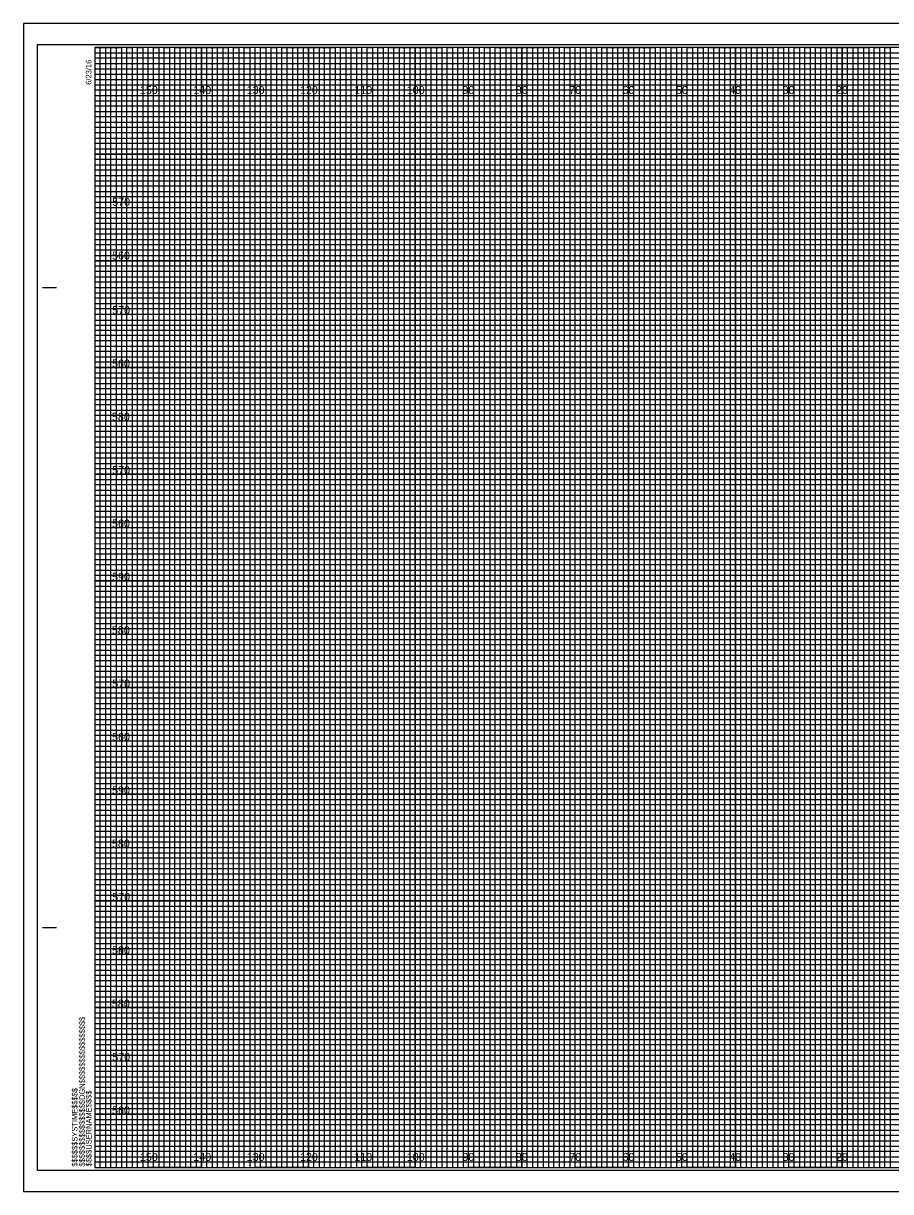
# Model space of a CAD drawing. Extents: x -13 to 323, y -5 to 215.
# Drawn here: x -13.4 to 149.1, y -4.5 to 214.5 of the extents above; entities that cross this region are included whole.
import ezdxf

# ---------------------------------------------------------------- set-up
doc = ezdxf.new("R2010")
doc.units = 0
for name, color, linetype in [('Exist Cross Section Cell', 7, 'Continuous'), ('Exist XS Center Line Elevation Label', 7, 'Continuous'), ('Exist XS Ground Line', 7, 'Continuous'), ('Prop XS Ditch Standard Text', 7, 'Continuous'), ('Prop XS Dump Level', 7, 'Continuous'), ('Prop XS Finish Grade', 7, 'Continuous'), ('Prop XS Finish Grade Earthwork', 7, 'Continuous'), ('Prop XS SE Text', 7, 'Continuous'), ('Prop XS Side Slope Text', 7, 'Continuous'), ('Prop XS SS Elevation Text', 7, 'Continuous'), ('Prop XS Subgrade Earthwork', 7, 'Continuous')]:
    doc.layers.add(name, color=color, linetype=linetype)

msp = doc.modelspace()

# ---------------------------------------------------------------- linework, layer by layer
at = {"layer": 'Exist Cross Section Cell'}
for points in [[(0, 210), (5, 210), (5, 0), (15, 0), (15, 210), (25, 210), (25, 0), (35, 0), (35, 210), (45, 210), (45, 0), (55, 0), (55, 210), (65, 210), (65, 0), (75, 0), (75, 210), (85, 210), (85, 0), (95, 0), (95, 210), (105, 210), (105, 0), (115, 0), (115, 210), (125, 210), (125, 0), (135, 0), (135, 210), (145, 210), (145, 0), (155, 0)], [(0, 205), (275, 205)], [(0, 185), (320, 185), (320, 195), (0, 195)], [(0, 165), (320, 165), (320, 175), (0, 175)], [(0, 145), (320, 145), (320, 155), (0, 155)], [(0, 125), (320, 125), (320, 135), (0, 135)], [(0, 105), (320, 105), (320, 115), (0, 115)], [(0, 85), (320, 85), (320, 95), (0, 95)], [(0, 65), (320, 65), (320, 75), (0, 75)], [(0, 45), (320, 45), (320, 55), (0, 55)], [(0, 25), (320, 25), (320, 35), (0, 35)], [(0, 5), (320, 5), (320, 15), (0, 15)]]:
    msp.add_lwpolyline(points, dxfattribs=at)
at = {"layer": 'Exist XS Center Line Elevation Label'}
for p, q in [((10, 210), (0, 210)), ((10, 0), (10, 210)), ((30, 210), (20, 210)), ((20, 210), (20, 0)), ((30, 0), (30, 210)), ((50, 210), (40, 210)), ((40, 210), (40, 0)), ((50, 0), (50, 210)), ((70, 210), (60, 210)), ((60, 210), (60, 0)), ((70, 0), (70, 210)), ((90, 210), (80, 210)), ((80, 210), (80, 0)), ((90, 0), (90, 210)), ((110, 210), (100, 210)), ((100, 210), (100, 0)), ((110, 0), (110, 210)), ((130, 210), (120, 210)), ((120, 210), (120, 0)), ((130, 0), (130, 210)), ((150, 210), (140, 210)), ((140, 210), (140, 0)), ((20, 0), (10, 0)), ((40, 0), (30, 0)), ((60, 0), (50, 0)), ((80, 0), (70, 0)), ((100, 0), (90, 0)), ((120, 0), (110, 0)), ((140, 0), (130, 0))]:
    msp.add_line(p, q, dxfattribs=at)
for points in [[(0, 200), (320, 200), (320, 190), (0, 190)], [(0, 180), (320, 180), (320, 170), (0, 170)], [(0, 160), (320, 160), (320, 150), (0, 150)], [(0, 140), (320, 140), (320, 130), (0, 130)], [(0, 120), (320, 120), (320, 110), (0, 110)], [(0, 100), (320, 100), (320, 90), (0, 90)], [(0, 80), (320, 80), (320, 70), (0, 70)], [(0, 60), (320, 60), (320, 50), (0, 50)], [(0, 40), (320, 40), (320, 30), (0, 30)], [(0, 20), (320, 20), (320, 10), (0, 10)]]:
    msp.add_lwpolyline(points, dxfattribs=at)
at = {"layer": 'Prop XS Ditch Standard Text'}
for points in [[(0, 0), (1, 0), (1, 210), (2, 210), (2, 0)], [(2, 0), (3, 0), (3, 210), (4, 210), (4, 0)], [(5, 0), (6, 0), (6, 210), (7, 210), (7, 0)], [(7, 0), (8, 0), (8, 210), (9, 210), (9, 0)], [(10, 0), (11, 0), (11, 210), (12, 210), (12, 0)], [(12, 0), (13, 0), (13, 210), (14, 210), (14, 0)], [(15, 0), (16, 0), (16, 210), (17, 210), (17, 0)], [(17, 0), (18, 0), (18, 210), (19, 210), (19, 0)], [(20, 0), (21, 0), (21, 210), (22, 210), (22, 0)], [(22, 0), (23, 0), (23, 210), (24, 210), (24, 0)], [(25, 0), (26, 0), (26, 210), (27, 210), (27, 0)], [(27, 0), (28, 0), (28, 210), (29, 210), (29, 0)], [(30, 0), (31, 0), (31, 210), (32, 210), (32, 0)], [(32, 0), (33, 0), (33, 210), (34, 210), (34, 0)], [(35, 0), (36, 0), (36, 210), (37, 210), (37, 0)], [(37, 0), (38, 0), (38, 210), (39, 210), (39, 0)], [(40, 0), (41, 0), (41, 210), (42, 210), (42, 0)], [(42, 0), (43, 0), (43, 210), (44, 210), (44, 0)], [(45, 0), (46, 0), (46, 210), (47, 210), (47, 0)], [(47, 0), (48, 0), (48, 210), (49, 210), (49, 0)], [(50, 0), (51, 0), (51, 210), (52, 210), (52, 0)], [(52, 0), (53, 0), (53, 210), (54, 210), (54, 0)], [(55, 0), (56, 0), (56, 210), (57, 210), (57, 0)], [(57, 0), (58, 0), (58, 210), (59, 210), (59, 0)], [(60, 0), (61, 0), (61, 210), (62, 210), (62, 0)], [(62, 0), (63, 0), (63, 210), (64, 210), (64, 0)], [(65, 0), (66, 0), (66, 210), (67, 210), (67, 0)], [(67, 0), (68, 0), (68, 210), (69, 210), (69, 0)], [(70, 0), (71, 0), (71, 210), (72, 210), (72, 0)], [(72, 0), (73, 0), (73, 210), (74, 210), (74, 0)], [(75, 0), (76, 0), (76, 210), (77, 210), (77, 0)], [(77, 0), (78, 0), (78, 210), (79, 210), (79, 0)], [(80, 0), (81, 0), (81, 210), (82, 210), (82, 0)], [(82, 0), (83, 0), (83, 210), (84, 210), (84, 0)], [(85, 0), (86, 0), (86, 210), (87, 210), (87, 0)], [(87, 0), (88, 0), (88, 210), (89, 210), (89, 0)], [(90, 0), (91, 0), (91, 210), (92, 210), (92, 0)], [(92, 0), (93, 0), (93, 210), (94, 210), (94, 0)], [(95, 0), (96, 0), (96, 210), (97, 210), (97, 0)], [(97, 0), (98, 0), (98, 210), (99, 210), (99, 0)], [(100, 0), (101, 0), (101, 210), (102, 210), (102, 0)], [(102, 0), (103, 0), (103, 210), (104, 210), (104, 0)], [(105, 0), (106, 0), (106, 210), (107, 210), (107, 0)], [(107, 0), (108, 0), (108, 210), (109, 210), (109, 0)], [(110, 0), (111, 0), (111, 210), (112, 210), (112, 0)], [(112, 0), (113, 0), (113, 210), (114, 210), (114, 0)], [(115, 0), (116, 0), (116, 210), (117, 210), (117, 0)], [(117, 0), (118, 0), (118, 210), (119, 210), (119, 0)], [(120, 0), (121, 0), (121, 210), (122, 210), (122, 0)], [(122, 0), (123, 0), (123, 210), (124, 210), (124, 0)], [(125, 0), (126, 0), (126, 210), (127, 210), (127, 0)], [(127, 0), (128, 0), (128, 210), (129, 210), (129, 0)], [(130, 0), (131, 0), (131, 210), (132, 210), (132, 0)], [(132, 0), (133, 0), (133, 210), (134, 210), (134, 0)], [(135, 0), (136, 0), (136, 210), (137, 210), (137, 0)], [(137, 0), (138, 0), (138, 210), (139, 210), (139, 0)], [(140, 0), (141, 0), (141, 210), (142, 210), (142, 0)], [(142, 0), (143, 0), (143, 210), (144, 210), (144, 0)], [(145, 0), (146, 0), (146, 210), (147, 210), (147, 0)], [(147, 0), (148, 0), (148, 210), (149, 210), (149, 0)]]:
    msp.add_lwpolyline(points, dxfattribs=at)
at = {"layer": 'Prop XS Dump Level'}
for p, q in [((-9.8, 165), (-7.3, 165)), ((-9.7, 165), (-7.2, 165)), ((-9.8, 45), (-7.3, 45)), ((-9.7, 45), (-7.2, 45)), ((0, 0), (0, 0)), ((0, 0), (0, 0)), ((0, 0), (0, 0)), ((0, 0), (0, 0)), ((0, 0), (0, 0)), ((0, 0), (0, 0)), ((0, 0), (0, 0))]:
    msp.add_line(p, q, dxfattribs=at)
msp.add_lwpolyline([(320, 210), (0, 210), (0, 0), (320, 0)], close=True, dxfattribs=at)
at = {"layer": 'Prop XS Finish Grade'}
for p, q in [((323.3, 214.5), (-13.4, 214.5)), ((-13.4, 214.5), (-13.4, -4.5)), ((-13.4, -4.5), (323.3, -4.5))]:
    msp.add_line(p, q, dxfattribs=at)
at = {"layer": 'Prop XS Finish Grade Earthwork'}
for p, q in [((10, 0), (10, 210)), ((20, 0), (20, 210)), ((30, 0), (30, 210)), ((40, 0), (40, 210)), ((50, 0), (50, 210)), ((60, 0), (60, 210)), ((70, 0), (70, 210)), ((80, 0), (80, 210)), ((90, 0), (90, 210)), ((100, 0), (100, 210)), ((110, 0), (110, 210)), ((120, 0), (120, 210)), ((130, 0), (130, 210)), ((140, 0), (140, 210)), ((0, 200), (320, 200)), ((0, 190), (320, 190)), ((0, 180), (320, 180)), ((0, 170), (320, 170)), ((0, 160), (320, 160)), ((0, 150), (320, 150)), ((0, 140), (320, 140)), ((0, 130), (320, 130)), ((0, 120), (320, 120)), ((0, 110), (320, 110)), ((0, 100), (320, 100)), ((0, 90), (320, 90)), ((0, 80), (320, 80)), ((0, 70), (320, 70)), ((0, 60), (320, 60)), ((0, 50), (320, 50)), ((0, 40), (320, 40)), ((0, 30), (320, 30)), ((0, 20), (320, 20)), ((0, 10), (320, 10))]:
    msp.add_line(p, q, dxfattribs=at)
at = {"layer": 'Prop XS SE Text'}
for p, q in [((0, 209), (260, 209)), ((260, 207.98), (0, 207.98)), ((0, 207.98), (0, 207)), ((0, 207), (260, 207)), ((260, 205.89), (0, 205.89)), ((0, 205.89), (0, 204)), ((0, 204), (320, 204))]:
    msp.add_line(p, q, dxfattribs=at)
for points in [[(0, 203), (270, 203), (320, 203), (320, 202), (0, 202)], [(0, 201), (320, 201), (320, 199), (0, 199)], [(0, 198), (320, 198), (320, 197), (0, 196.98)], [(0, 196), (320, 196), (320, 194), (0, 194)], [(0, 193), (320, 193), (320, 192), (0, 192)], [(0, 191), (320, 191), (320, 189), (0, 189)], [(0, 188), (320, 188), (320, 187), (0, 187)], [(0, 186), (320, 186), (320, 184), (0, 184)], [(0, 183), (320, 183), (320, 182), (0, 182)], [(0, 181), (320, 181), (320, 179), (0, 179)], [(0, 178), (320, 178), (320, 177), (0, 177)], [(0, 176), (320, 176), (320, 173.95), (320, 173), (320, 172), (0, 172)], [(0, 174), (320, 174), (320, 173), (0, 173)], [(0, 171), (320, 171), (320, 169), (0, 169.03)], [(0, 169.03), (320, 169), (320, 168), (0, 168)], [(0, 167), (320, 167), (320, 166), (0, 166)], [(0, 164), (320, 164), (320, 163), (0, 163)], [(0, 162), (320, 162), (320, 161), (0, 161)], [(-0.07, 158.89), (320, 158.89), (320, 157.88), (-0.07, 157.88)], [(0, 157), (320, 157), (320, 156), (0, 156)], [(0, 154), (320, 154), (320, 153), (0, 153)], [(0, 152), (320, 152), (320, 151), (0, 151)], [(0, 149), (320, 149), (320, 148), (0, 148)], [(0, 147), (320, 147), (320, 146), (0, 146)], [(0, 144), (320, 144), (320, 143), (0, 143)], [(0, 142), (320, 142), (320, 141), (0, 141)], [(0, 139), (320, 139), (319.99, 137.98), (0, 138)], [(0, 137), (320, 137), (320, 136), (0, 136)], [(0, 134), (320, 134), (320, 133), (0, 133)], [(0, 132), (320, 132), (320, 131), (0, 131)], [(0, 129), (320, 129), (320, 128), (0, 128)], [(0, 127), (320, 127), (320, 126), (0, 126)], [(0, 124), (320, 124), (320, 123), (0, 123)], [(0, 122), (320, 122), (320, 121), (0, 121)], [(0, 119), (320, 119), (320, 118), (0, 118)], [(0, 116.99), (320.07, 116.91), (320, 116), (0, 116)], [(0, 114), (320, 114), (320, 113), (0, 113)], [(0, 112), (320, 112), (320, 111), (0, 111)], [(0, 109), (320, 109), (320, 108), (0, 108)], [(0, 107), (320, 107), (320, 106), (0, 106)], [(0, 104), (320, 104), (320, 103), (0, 103)], [(0, 102), (320, 102), (320, 101), (0, 101)], [(0, 99), (320, 99), (320, 98), (0, 98)], [(0, 97), (320, 97), (320, 96), (0, 96)], [(0, 94), (320, 94), (320, 93), (0, 93)], [(0, 92), (320, 92), (320, 91), (0, 91)], [(0, 89), (320, 89), (320, 88), (0, 88)], [(0, 87), (320, 87), (320, 86), (0, 86)], [(0, 84), (320, 84), (320, 83), (0, 83)], [(0, 82), (320, 82), (320, 81), (0, 81)], [(0, 79), (320, 79), (319.99, 77.98), (0, 78)], [(0, 77), (320, 77), (320, 76), (0, 76)], [(0, 74), (320, 74), (320, 73), (0, 73)], [(0, 72), (320, 72), (320, 71), (0, 71)], [(0, 69), (320, 69), (320, 68), (0, 68)], [(0, 67), (320, 67), (320, 66), (0, 66)], [(0, 64), (320, 64), (320, 63), (0, 63)], [(0, 62), (320, 62), (320, 61), (0, 61)], [(0, 59), (320, 59), (320, 58), (0, 58)], [(0, 56.99), (320.07, 56.91), (320, 56), (0, 56)], [(0, 54), (320, 54), (320, 53), (0, 53)], [(0, 52), (320, 52), (320, 51), (0, 51)], [(0, 49), (320, 49), (320, 48), (0, 48)], [(0, 47), (320, 47), (320, 46), (0, 46)], [(0, 44), (320, 44), (320, 43), (0, 43)], [(0, 42), (320, 42), (320, 41), (0, 41)], [(0, 39), (320, 39), (320, 38), (0, 38)], [(0, 37), (320, 37), (320, 36), (0, 36)], [(0, 34), (320, 34), (320, 33), (0, 33)], [(0, 32), (320, 32), (320, 31), (0, 31)], [(0, 29), (320, 29), (320, 28), (0, 28)], [(0, 27), (320, 27), (320, 26), (0, 26)], [(0, 24), (320, 24), (320, 23), (0, 23)], [(0, 22), (320, 22), (320, 21), (0, 21)], [(0, 19), (320, 19), (320, 18), (0, 18)], [(0, 17), (320, 17), (320, 16), (0, 16)], [(0, 14), (320, 14), (320, 13), (0, 13)], [(0, 12), (320, 12), (320, 11), (0, 11)], [(0, 9), (320, 9), (320, 8), (0, 8)], [(0, 7), (320, 7), (320, 6), (0, 6)], [(0, 4), (320, 4), (320, 3), (0, 3)], [(0, 2), (320, 2), (320, 1), (0, 1)]]:
    msp.add_lwpolyline(points, dxfattribs=at)
at = {"layer": 'Prop XS Side Slope Text'}
msp.add_lwpolyline([(-13.4, -4.5), (323.3, -4.5), (323.3, 214.5), (-13.4, 214.5)], close=True, dxfattribs=at)
at = {"layer": 'Prop XS SS Elevation Text'}
msp.add_lwpolyline([(-10.8, -0.5), (322.4, -0.5), (322.4, 210.5), (-10.8, 210.5)], close=True, dxfattribs=at)

# ---------------------------------------------------------------- texts
at = {"layer": 'Exist XS Ground Line'}
for s, p in [('150', (8.44, 201.25)), ('140', (18.44, 201.25)), ('130', (28.44, 201.25)), ('120', (38.44, 201.25)), ('110', (48.62, 201.25)), ('100', (58.44, 201.25)), ('90', (68.86, 201.25)), ('80', (78.86, 201.25)), ('70', (88.86, 201.25)), ('60', (98.86, 201.25)), ('50', (108.86, 201.25)), ('40', (118.86, 201.25)), ('30', (128.86, 201.25)), ('20', (138.86, 201.25)), ('150', (8.44, 1.25)), ('140', (18.44, 1.25)), ('130', (28.44, 1.25)), ('120', (38.44, 1.25)), ('110', (48.62, 1.25)), ('100', (58.44, 1.25)), ('90', (68.86, 1.25)), ('80', (78.86, 1.25)), ('70', (88.86, 1.25)), ('60', (98.86, 1.25)), ('50', (108.86, 1.25)), ('40', (118.86, 1.25)), ('30', (128.86, 1.25)), ('20', (138.86, 1.25))]:
    msp.add_text(s, height=1.5, dxfattribs=at).set_placement(p)
at = {"layer": 'Prop XS Dump Level'}
for s, p in [('6/23/16', (-0.65, 203)), ('$$$$$$$$$$$$$$$$DGN$$$$$$$$$$$$$$$$', (-1.88, 0.18)), ('$$$$$$SYSTIME$$$$$', (-3.26, 0.18)), ('$$$$USERNAME$$$$', (-0.62, 0.23))]:
    msp.add_text(s, height=1.05, rotation=90, dxfattribs=at).set_placement(p)
at = {"layer": 'Prop XS Subgrade Earthwork'}
for s, p in [('570', (3.25, 180.3)), ('560', (3.22, 170.23)), ('570', (3.25, 160)), ('560', (3.22, 150)), ('580', (3.19, 140)), ('570', (3.25, 130)), ('560', (3.22, 120)), ('590', (3.22, 110)), ('580', (3.19, 100)), ('570', (3.25, 90)), ('560', (3.22, 80)), ('590', (3.22, 70)), ('580', (3.19, 60)), ('570', (3.25, 50)), ('590', (3.22, 40)), ('560', (3.22, 40)), ('580', (3.19, 30)), ('570', (3.25, 20)), ('560', (3.22, 10))]:
    msp.add_text(s, height=1.5, dxfattribs=at).set_placement(p)

doc.saveas('drawing.dxf')
